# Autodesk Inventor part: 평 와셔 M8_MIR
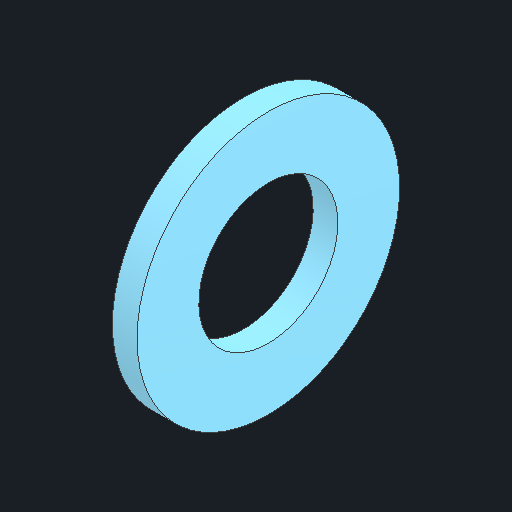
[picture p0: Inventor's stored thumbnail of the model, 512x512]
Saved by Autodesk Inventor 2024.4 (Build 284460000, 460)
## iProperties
Created: 2025-10
Part Number: 평 와셔 M8_MIR
Material: 강철, 연강
Description: 평면 와셔
Document SubType Name: Modeling
Designer: user
Density: 7.85 g/cm^3
Appearance: 기본값
Author: jhkim
Sending System: Autodesk Inventor 2026
Preprocessor: ST-DEVELOPER v20.1
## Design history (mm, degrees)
derived "평 와셔 M8.ipt"
feature "솔리드1::평 와셔 M8.ipt" dims "d0" = 10
tag "피쳐 태그1"
node "솔리드1"
